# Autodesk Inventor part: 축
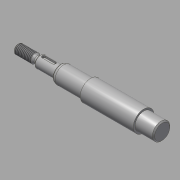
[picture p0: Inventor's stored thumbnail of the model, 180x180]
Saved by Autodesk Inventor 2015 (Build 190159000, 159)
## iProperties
Created: 2015-11
Part Number: 축
Material: 강철, 연강
Document SubType Name: Modeling
Designer: mduedu
Density: 1 g/cm^3
Appearance: 강철
Author: mduedu
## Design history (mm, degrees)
sketch "스케치1"
  geometry: L1 (-86, 0)-(86, 0); L2 (-86, 0)-(-86, 4); L3 (-86, 4)-(-70.732, 4); L4 (-70.732, 4)-(-69, 3); L5 (-69, 3)-(-67, 3); L6 (-67, 3)-(-67, 5); L7 (-67, 5)-(-49, 5); L8 (-49, 5)-(-49, 6.55); L9 (-47.355, 7.5)-(-23, 7.5); L10 (-23, 7.5)-(-23, 9); L11 (0, 0)-(0, 9); L12 (86, 4)-(70.732, 4); L13 (70.732, 4)-(69, 3); L14 (69, 3)-(67, 3); L15 (67, 3)-(67, 5); L16 (67, 5)-(49, 5); L17 (23, 7.5)-(23, 9); L18 (86, 0)-(86, 4); L19 (-23, 9)-(23, 9); L20 (-49, 6.55)-(-47.355, 7.5); L21 (47.355, 7.5)-(23, 7.5); L22 (49, 6.55)-(47.355, 7.5); L23 (49, 5)-(49, 6.55); 1 further point
  constraints: 46 end point, 10 symmetric about line, 6 perpendicular, 5 parallel, 2 midpoint, 1 coincident, 1 horizontal
  dimensions: "d0" = 172 distance of L1.start L1.end (derived); "d1" = 8 diameter of L3 L1; "d2" = 30 deg angle of L4 L5; "d3" = 6 diameter of L5 L1; "d4" = 10 diameter of L7 L1; "d5" = 15 diameter of L9 L1; "d6" = 18 diameter of L19 L1; "d8" = 18 distance of L6.end L7.end; "d9" = 46 distance of L10.end L17.end; "d10" = 2 distance of L4.end L5.end; "d11" = 17 distance from line of L4.end L2; "d16" = 13.1 diameter of L8.end L1; "d17" = 30 deg angle of L20 L9; "d18" = 26 distance between parallel lines of L10 L8
revolve "회전1" sketch "스케치1" stored, may be unused: angle "d12" = 90 deg
chamfer "모따기1" distance "d13" = 1; stored, may be unused: second distance "d14" = 2, angle "d15" = 45 deg
fillet "모깎기1" dims "d19" = 4, "d20" = 0.5
node "작업 평면1"
sketch "스케치2" dims "d23" = 12
  geometry: L1 (-5.5, 1.5)-(3.5, 1.5); L2 (3.5, 1.5)-(3.5, -1.5); L3 (3.5, -1.5)-(-5.5, -1.5); L4 (-5.5, -1.5)-(-5.5, 1.5); L5 (-9, -4)-(-9, 4) reference; 3 further points
  constraints: 8 end point, 2 midpoint, 2 parallel, 2 vertical alignment, 1 horizontal, 1 perpendicular, 4 other
  dimensions: "d21" = 3 distance between parallel lines of L3 L1; "d24" = 2 dimension on L5
extrude "돌출1" cut sketch "스케치2" distance "d25" = 1.8; taper "d26" = 0 deg
feature "스레드1" dims "d27" = 10, "d28" = 0
feature "스레드2" dims "d29" = 10, "d30" = 0
chamfer "모따기2" distance "d31" = 1; stored, may be unused: second distance "d32" = 2, angle "d33" = 45 deg
node "작업 평면2"
sketch "스케치3"
  geometry: C1 r 7.5 at (0, 0) reference; 1 further point
extrude "돌출2" cut sketch "스케치3" stored distance "d36" = 10; taper "d37" = 0 deg
chamfer "모따기3" distance "d38" = 1; stored, may be unused: second distance "d39" = 2, angle "d40" = 45 deg
node "솔리드1"
mirror "대칭1"
node "절단 모서리 투영1"
other parameters: "d35" = 16
